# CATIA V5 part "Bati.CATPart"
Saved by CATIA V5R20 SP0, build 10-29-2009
Part number: Bati
Bounding box of the stored display mesh (mm): x -40 to 15, y 0 to 190.834, z 0 to 239.347
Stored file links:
  C:\Users\thinkmotion1\Desktop\IAO OK\IAO_2010_1458_splanchena\Correction_Khaled\Bati.CATPart
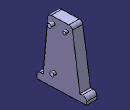
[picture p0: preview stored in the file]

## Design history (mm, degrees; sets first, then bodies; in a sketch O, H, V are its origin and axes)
Body1 (main body)
  Sketch1 on yz-plane, origin (0, 0, 0), H (0, 1, 0), V (0, 0, 1)
    line L1 (0, 0) -> (190.8339, 7.2747)
    line L2 (0, 0) -> (0, 12.6633)
    line L3 (14.5024, 27.6551) -> (25.0874, 28.0064)
    line L4 (190.4037, 18.5586) -> (190.8339, 7.2747)
    arc A1 centre (175.4146, 17.9872) radius 15 from (190.4037, 18.5586) to (174.9171, 32.979) ccw
    arc A2 centre (15, 12.6633) radius 15 from (0, 12.6633) to (14.5024, 27.6551) cw
    line L5 (165.205, 32.6567) -> (136.3185, 228.2554)
    point P8 (165.205, 32.6567)
    line L6 (25.0874, 28.0064) -> (41.1298, 223.9944)
    line L7 (54.5709, 236.8429) -> (122.9824, 239.3474)
    arc A3 centre (123.458, 226.3561) radius 13 from (122.9824, 239.3474) to (136.3185, 228.2554) cw
    arc A4 centre (55.0831, 222.8523) radius 14 from (41.1298, 223.9944) to (54.5709, 236.8429) cw
    line L8 (165.205, 32.6567) -> (174.9171, 32.979)
    radius A1 = 15
    radius A2 = 15
    radius A3 = 13
    radius A4 = 14
    vertical: L2 V
    perpendicularity: L4 L1
    tangency: A1 L4, A1 L3, A2 L2, A2 L3, A3 L7, A3 L5, A4 L6, A4 L7
    coincidence: P8 L3, L3 L8
  Pad1: profile Sketch1, direction (-1, 0, 0), length 40
  Sketch2 on start face of Pad1, origin (0, 0, 0), H (0, 1, 0), V (0, 0, 1)
    circle A1 centre (67.0523, 52.9099) radius 7.5
    radius A1 = 7.5
  Pad2: profile Sketch2, direction (1, 0, 0), length 10
  Sketch3 on start face of Pad1, origin (0, 0, 0), H (0, 1, 0), V (0, 0, 1)
    circle A1 centre (62.4887, 213.3176) radius 7.5
    radius A1 = 7.5
  Pad3: profile Sketch3, direction (1, 0, 0), length 15
  Sketch4 on start face of Pad1, origin (0, 0, 0), H (0, 1, 0), V (0, 0, 1)
    circle A1 centre (114.9085, 213.8122) radius 6
    radius A1 = 6
  Pad4: profile Sketch4, direction (1, 0, 0), length 10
